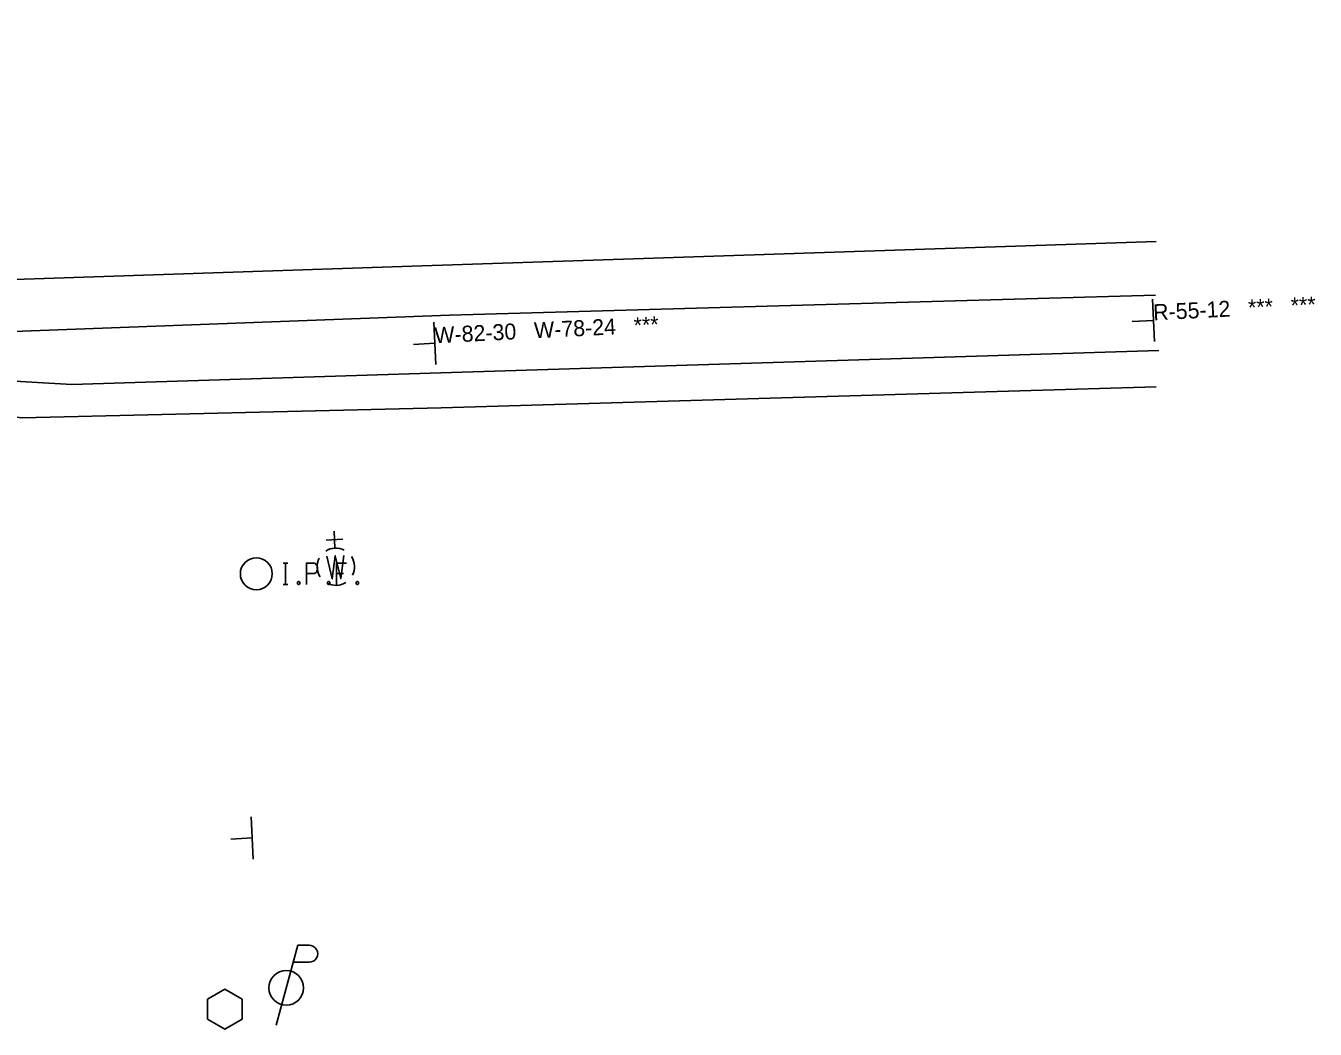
# Model space of a CAD drawing. Extents: x 129284 to 131418, y 268402 to 269012.
# Drawn here: x 129903.4 to 130000.1, y 268695.9 to 268771.2 of the extents above; entities that cross this region are included whole.
import ezdxf

# ---------------------------------------------------------------- set-up
doc = ezdxf.new("R2010")
doc.units = 0
for name, color, linetype in [('Default', 7, 'Continuous'), ('Level 63', 7, 'Continuous'), ('PV_X_Curb', 7, 'Continuous'), ('PV_X_EOP', 7, 'Continuous'), ('PV_X_Walk', 7, 'Continuous'), ('RD_X_Cells', 7, 'Continuous'), ('SV_X_Mon_Cells_Found', 7, 'Continuous'), ('UT_X_Electric_Cells', 7, 'Continuous')]:
    doc.layers.add(name, color=color, linetype=linetype)

# ---------------------------------------------------------------- blocks, each defined once
blk = doc.blocks.new('POINT_DISPLAY')
at = {"layer": 'Default'}
blk.add_line((0, 0), (0, 0), dxfattribs=at)

msp = doc.modelspace()

# ---------------------------------------------------------------- linework, layer by layer
at = {"layer": 'PV_X_Curb'}
msp.add_lwpolyline([(129878.906, 268770.8), (129879.531, 268764.095), (129882.078, 268756.812), (129886.484, 268750.969), (129888.311, 268749.54), (129890.872, 268747.842), (129892.255, 268747.025), (129898.243, 268744.826), (129906.828, 268744.332), (129934.518, 268745.209), (129988.405, 268746.887)], dxfattribs=at)
at = {"layer": 'PV_X_EOP'}
msp.add_lwpolyline([(129988.216, 268744.138), (129934.567, 268742.581), (129903.119, 268741.827), (129895.847, 268742.655), (129887.846, 268746.546), (129882.242, 268751.95), (129878.155, 268759.486), (129877.014, 268764.049), (129876.392, 268771.108)], dxfattribs=at)
at = {"layer": 'PV_X_Walk'}
for p, q in [((129987.934, 268750.737), (129988.092, 268747.541)), ((129987.934, 268750.737), (129988.092, 268747.541)), ((129987.934, 268750.737), (129988.092, 268747.541)), ((129988.013, 268749.139), (129986.415, 268749.06)), ((129988.013, 268749.139), (129986.415, 268749.06)), ((129988.013, 268749.139), (129986.415, 268749.06)), ((129933.994, 268749.014), (129934.152, 268745.818)), ((129933.994, 268749.014), (129934.152, 268745.818)), ((129933.994, 268749.014), (129934.152, 268745.818)), ((129934.073, 268747.416), (129932.475, 268747.337)), ((129934.073, 268747.416), (129932.475, 268747.337)), ((129934.073, 268747.416), (129932.475, 268747.337)), ((129920.297, 268711.892), (129920.455, 268708.696)), ((129920.297, 268711.892), (129920.455, 268708.696)), ((129920.297, 268711.892), (129920.455, 268708.696)), ((129920.376, 268710.294), (129918.778, 268710.215)), ((129920.376, 268710.294), (129918.778, 268710.215)), ((129920.376, 268710.294), (129918.778, 268710.215))]:
    msp.add_line(p, q, dxfattribs=at)
for points in [[(129879.203, 268770.9), (129879.872, 268764.046), (129882.204, 268757.074), (129885.153, 268753.016), (129888.278, 268749.968), (129891.278, 268747.89), (129898.117, 268745.178), (129902.576, 268744.661), (129902.46, 268748.309), (129935.186, 268749.52), (129988.168, 268751.021)], [(129988.201, 268755.066), (129931.625, 268753.184), (129895.025, 268751.949), (129889.742, 268756.691), (129886.304, 268761.968), (129885.475, 268764.812), (129884.895, 268771.244)]]:
    msp.add_lwpolyline(points, dxfattribs=at)
at = {"layer": 'RD_X_Cells'}
for p, q in [((129927.183, 268732.714), (129925.913, 268732.651)), ((129926.581, 268732.047), (129926.518, 268733.317))]:
    msp.add_line(p, q, dxfattribs=at)
for points in [[(129925.973, 268731.436), (129926.376, 268729.731), (129926.609, 268731.468), (129927.014, 268729.762), (129927.245, 268731.499)], [(129917.017, 268696.694), (129918.315, 268695.944), (129919.614, 268696.694), (129919.614, 268698.194), (129918.315, 268698.944), (129917.017, 268698.194), (129917.017, 268696.694)]]:
    msp.add_lwpolyline(points, dxfattribs=at)
for start, end in [(62.84864, 122.84602), (152.84864, 212.81192), (332.84864, 32.81192), (242.81454, 302.81192)]:
    msp.add_arc((129926.649, 268730.65), 1.4, start, end, dxfattribs=at)
at = {"layer": 'SV_X_Mon_Cells_Found'}
for points in [[(129922.698, 268730.921), (129923.051, 268730.921)], [(129922.875, 268729.321), (129922.875, 268730.921)], [(129924.44, 268729.321), (129924.44, 268730.921), (129924.969, 268730.921), (129925.024, 268730.908), (129925.101, 268730.883), (129925.134, 268730.858), (129925.167, 268730.832), (129925.212, 268730.77), (129925.245, 268730.706), (129925.267, 268730.606), (129925.267, 268730.454), (129925.256, 268730.404), (129925.234, 268730.329), (129925.189, 268730.24), (129925.145, 268730.203), (129925.112, 268730.177), (129925.057, 268730.152), (129924.969, 268730.14), (129924.44, 268730.14)], [(129927.449, 268730.921), (129926.689, 268730.921), (129926.689, 268729.321)], [(129926.689, 268730.14), (129927.229, 268730.14)], [(129922.698, 268729.321), (129923.051, 268729.321)], [(129923.834, 268729.535), (129923.889, 268729.535), (129923.922, 268729.51), (129923.955, 268729.459), (129923.955, 268729.396), (129923.922, 268729.346), (129923.889, 268729.321), (129923.834, 268729.321), (129923.801, 268729.346), (129923.768, 268729.396), (129923.768, 268729.459), (129923.801, 268729.51), (129923.834, 268729.535)], [(129926.082, 268729.535), (129926.137, 268729.535), (129926.171, 268729.51), (129926.204, 268729.459), (129926.204, 268729.396), (129926.171, 268729.346), (129926.137, 268729.321), (129926.082, 268729.321), (129926.049, 268729.346), (129926.016, 268729.396), (129926.016, 268729.459), (129926.049, 268729.51), (129926.082, 268729.535)], [(129928.232, 268729.535), (129928.287, 268729.535), (129928.32, 268729.51), (129928.353, 268729.459), (129928.353, 268729.396), (129928.32, 268729.346), (129928.287, 268729.321), (129928.232, 268729.321), (129928.199, 268729.346), (129928.166, 268729.396), (129928.166, 268729.459), (129928.199, 268729.51), (129928.232, 268729.535)]]:
    msp.add_lwpolyline(points, dxfattribs=at)
msp.add_circle((129920.684, 268730.121), 1.2, dxfattribs=at)
at = {"layer": 'UT_X_Electric_Cells'}
for p, q in [((129923.789, 268702.243), (129922.182, 268696.243)), ((129923.789, 268702.243), (129924.639, 268702.243)), ((129923.447, 268700.969), (129924.639, 268700.969))]:
    msp.add_line(p, q, dxfattribs=at)
msp.add_circle((129922.932, 268699.044), 1.3, dxfattribs=at)
msp.add_arc((129924.651, 268701.606), 0.638, 268.8767, 91.1233, dxfattribs=at)

# ---------------------------------------------------------------- block references
at = {"layer": 'RD_X_Cells', "xscale": 3.9370000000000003, "yscale": 3.9370000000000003}
msp.add_blockref('POINT_DISPLAY', (129926.65, 268730.649), dxfattribs=at)

# ---------------------------------------------------------------- texts
at = {"layer": 'Level 63'}
for s, p in [('R-55-12   ***   ***', (129988.013, 268749.139)), ('R-55-12   ***   ***', (129988.013, 268749.139)), ('W-82-30   W-78-24   ***', (129934.073, 268747.416)), ('W-82-30   W-78-24   ***', (129934.073, 268747.416))]:
    msp.add_text(s, height=1.2, rotation=2.83028, dxfattribs=at).set_placement(p)

doc.saveas('drawing.dxf')
